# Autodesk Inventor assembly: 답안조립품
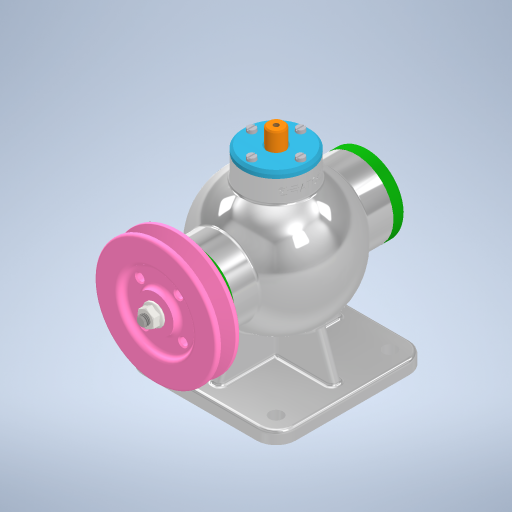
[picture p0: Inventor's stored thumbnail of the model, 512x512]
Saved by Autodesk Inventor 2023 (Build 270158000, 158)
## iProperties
Created: 2023-07
Part Number: 답안조립품
Document SubType Name: Assembly
Designer: Owner
Author: Owner
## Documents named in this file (16)
- C:\Users\Owner\Desktop\730711V1008\답안조립품.iam
- C:\Users\Owner\Desktop\730711V1008\본체.ipt
- C:\Users\Owner\Desktop\730711V1008\뒤커버.ipt
- C:\Users\Owner\Desktop\730711V1008\앞커버.ipt
- C:\Users\Owner\Desktop\730711V1008\상부커버.ipt
- C:\Users\Owner\Desktop\730711V1008\베어링- 6202.ipt
- KS B 2023 - 6202 - 15 x 35 x 11 - 7.8.ipt
- C:\Users\Owner\Desktop\730711V1008\칼라.ipt
- C:\Users\Owner\Desktop\730711V1008\편심축.ipt
- C:\Users\Owner\Desktop\730711V1008\키 4 x 4 x 12.ipt
- C:\Users\Owner\Desktop\730711V1008\오일실 15 30 7.ipt
- C:\Users\Owner\Desktop\730711V1008\V-벨트풀리.ipt
- C:\Users\Owner\Desktop\730711V1008\너트 M8.ipt
- C:\Users\Owner\Desktop\730711V1008\볼트 M4 x 16.ipt
- C:\Users\Owner\Desktop\730711V1008\볼트 M4 x 12.ipt
- C:\Users\Owner\Desktop\730711V1008\슬라이드.ipt
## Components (15 placed, 4 different names)
1. KS B 2023 - 6202 - 15 x 35 x 11 - 7.8:1
2. KS B 2023 - 6202 - 15 x 35 x 11 - 7.8:2
3. V-벨트풀리:1
4. ISO 4762 M4 x 16:1
5. ISO 4762 M4 x 16:2
6. ISO 4762 M4 x 16:3
7. ISO 4762 M4 x 16:4
8. ISO 4762 M4 x 16:5
9. ISO 4762 M4 x 16:6
10. ISO 4762 M4 x 16:7
11. ISO 4762 M4 x 16:9
12. KS B 1021 - 에 따름 ISO 1207 - 미터 A  M 4 x 12:1
13. KS B 1021 - 에 따름 ISO 1207 - 미터 A  M 4 x 12:2
14. KS B 1021 - 에 따름 ISO 1207 - 미터 A  M 4 x 12:3
15. KS B 1021 - 에 따름 ISO 1207 - 미터 A  M 4 x 12:4
